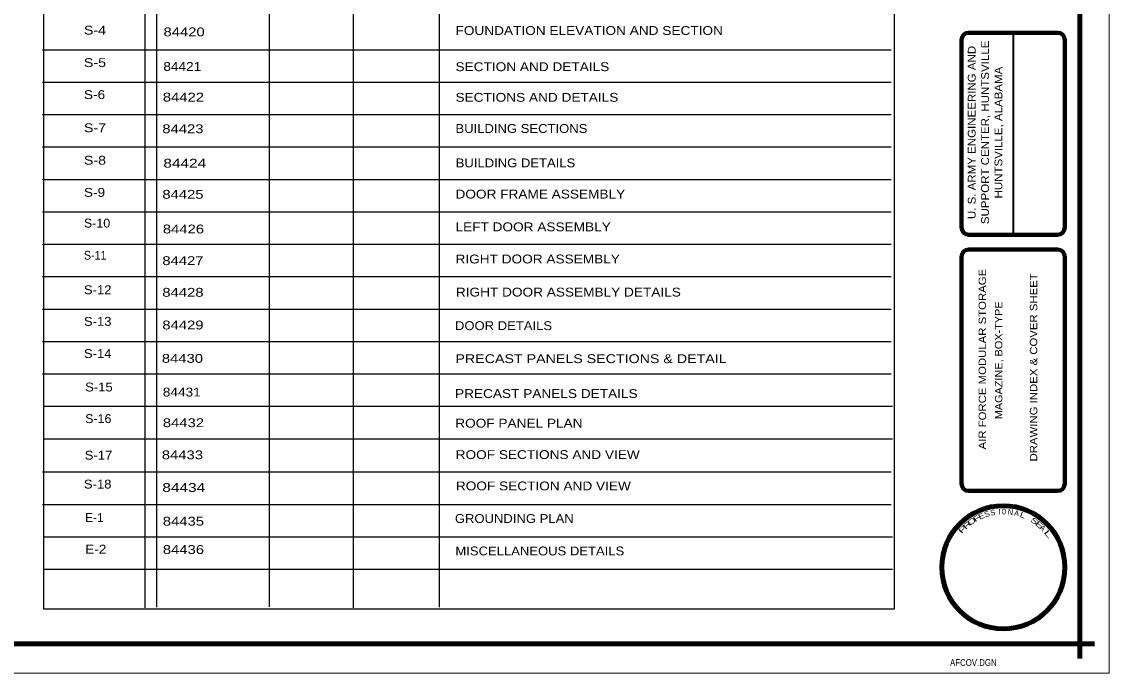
# Model space of a CAD drawing. Extents: x -153.1 to -120, y 360.9 to 384.2.
# Drawn here: x -137.36 to -119.98, y 360.85 to 371.27 of the extents above; entities that cross this region are included whole.
import ezdxf
from ezdxf.enums import TextEntityAlignment as Align

# ---------------------------------------------------------------- set-up
doc = ezdxf.new("R2010")
doc.units = 0
doc.header["$LTSCALE"] = 0.039
for name, color, linetype, lineweight in [('1', 7, 'Continuous', 80), ('3', 7, 'Continuous', 80), ('63', 7, 'Continuous', 25), ('8', 7, 'Continuous', 25)]:
    doc.layers.add(name, color=color, linetype=linetype, lineweight=lineweight)
doc.layers.add('7', color=7, linetype='Continuous')

msp = doc.modelspace()

# ---------------------------------------------------------------- linework, layer by layer
at = {"layer": '1'}
for p, q in [((-122.3375, 370.97314), (-122.3375, 367.98103)), ((-122.3375, 370.97314), (-122.3375, 367.98103)), ((-122.21937, 371.09124), (-120.80208, 371.09124)), ((-122.21937, 371.09124), (-120.80208, 371.09124)), ((-120.68396, 367.98103), (-120.68396, 370.97314)), ((-120.68396, 367.98103), (-120.68396, 370.97314)), ((-122.21937, 367.86293), (-120.80208, 367.86293)), ((-122.21937, 367.86293), (-120.80208, 367.86293)), ((-122.3375, 367.50859), (-122.3375, 363.8858)), ((-122.3375, 367.50859), (-122.3375, 363.8858)), ((-120.80208, 367.6267), (-122.21937, 367.6267)), ((-120.80208, 367.6267), (-122.21937, 367.6267)), ((-120.68396, 363.8858), (-120.68396, 367.50859)), ((-120.68396, 363.8858), (-120.68396, 367.50859)), ((-122.21937, 363.7677), (-120.80208, 363.7677)), ((-122.21937, 363.7677), (-120.80208, 363.7677))]:
    msp.add_line(p, q, dxfattribs=at)
at = {"layer": '1', "lineweight": 40}
msp.add_line((-121.51073, 371.09124), (-121.51073, 367.86293), dxfattribs=at)
msp.add_line((-121.51073, 371.09124), (-121.51073, 367.86293), dxfattribs=at)
at = {"layer": '1', "lineweight": 90}
msp.add_line((-120.44775, 361.32709), (-120.44775, 361.09086), dxfattribs=at)
msp.add_line((-120.44775, 361.32709), (-120.44775, 361.09086), dxfattribs=at)
msp.add_line((-120.44775, 361.32709), (-120.44775, 361.09086), dxfattribs=at)
at = {"layer": '1', "lineweight": 13}
msp.add_lwpolyline([(-153.08523, 360.85466), (-119.97531, 360.85466), (-119.97531, 384.24028), (-153.08523, 384.24028)], close=True, dxfattribs=at)
msp.add_lwpolyline([(-153.08523, 360.85466), (-119.97531, 360.85466), (-119.97531, 384.24028), (-153.08523, 384.24028)], close=True, dxfattribs=at)
msp.add_lwpolyline([(-153.08523, 360.85466), (-119.97531, 360.85466), (-119.97531, 384.24028), (-153.08523, 384.24028)], close=True, dxfattribs=at)
at = {"layer": '1', "lineweight": 90}
for points in [[(-152.02225, 383.76784), (-120.44775, 383.76784), (-120.44775, 361.32709)], [(-152.02225, 383.76784), (-120.44775, 383.76784), (-120.44775, 361.32709)], [(-152.02225, 383.76784), (-120.44775, 383.76784), (-120.44775, 361.32709)], [(-120.21152, 361.32709), (-120.44775, 361.32709), (-122.67215, 361.32709), (-152.02225, 361.32709)], [(-120.21152, 361.32709), (-120.44775, 361.32709), (-122.67215, 361.32709), (-152.02225, 361.32709)], [(-120.21152, 361.32709), (-120.44775, 361.32709), (-122.67215, 361.32709), (-152.02225, 361.32709)]]:
    msp.add_lwpolyline(points, dxfattribs=at)
msp.add_circle((-121.6682, 362.54754), 0.98424, dxfattribs=at)
msp.add_circle((-121.6682, 362.54754), 0.98424, dxfattribs=at)
at = {"layer": '1'}
for centre, start, end in [((-122.21937, 370.97314), 90, 180), ((-122.21937, 370.97314), 90, 180), ((-120.80206, 370.97314), 0, 90), ((-120.80206, 370.97314), 0, 90)]:
    msp.add_arc(centre, 0.11811, start, end, dxfattribs=at)
at = {"layer": '3'}
for centre, start, end in [((-122.21937, 367.98104), 180, 270), ((-122.21937, 367.98104), 180, 270), ((-120.80206, 367.98104), 270, 0), ((-120.80206, 367.98104), 270, 0), ((-122.21937, 367.5086), 90, 180), ((-122.21937, 367.5086), 90, 180), ((-120.80206, 367.5086), 0, 90), ((-120.80206, 367.5086), 0, 90), ((-122.21937, 363.8858), 180, 270), ((-122.21937, 363.8858), 180, 270), ((-120.80206, 363.8858), 270, 0), ((-120.80206, 363.8858), 270, 0)]:
    msp.add_arc(centre, 0.11811, start, end, dxfattribs=at)
at = {"layer": '63'}
msp.add_lwpolyline([(-137.00331, 374.8668), (-123.41131, 374.8668), (-123.41131, 361.87971), (-137.00331, 361.87971)], close=True, dxfattribs=at)
at = {"layer": '8'}
for p, q in [((-135.38806, 374.12059), (-135.38806, 361.89876)), ((-135.20612, 374.20461), (-135.20612, 361.90815)), ((-133.40354, 374.12059), (-133.40354, 361.91753)), ((-130.68806, 374.12059), (-130.68806, 361.90815)), ((-132.06006, 373.78197), (-132.06006, 361.89876)), ((-137.02615, 370.81895), (-123.46037, 370.81895)), ((-137.02615, 370.30093), (-123.46037, 370.30093)), ((-137.02615, 369.78291), (-123.46037, 369.78291)), ((-137.02615, 369.26491), (-123.46037, 369.26491)), ((-137.02615, 368.74689), (-123.46037, 368.74689)), ((-137.02615, 368.22886), (-123.46037, 368.22886)), ((-137.02615, 367.71084), (-123.46037, 367.71084)), ((-137.02615, 367.19284), (-123.46037, 367.19284)), ((-137.02615, 366.67482), (-123.46037, 366.67482)), ((-137.02615, 366.1568), (-123.46037, 366.1568)), ((-137.02615, 365.63878), (-123.46037, 365.63878)), ((-137.0066, 365.12076), (-123.44085, 365.12076)), ((-137.0066, 364.60276), (-123.44085, 364.60276)), ((-137.02615, 364.07118), (-123.46037, 364.07118)), ((-137.02615, 363.55316), (-123.46037, 363.55316)), ((-137.0066, 363.03516), (-123.44085, 363.03516)), ((-137.0066, 362.51714), (-123.44085, 362.51714))]:
    msp.add_line(p, q, dxfattribs=at)

# ---------------------------------------------------------------- texts
at = {"layer": '1', "width": 1.1}
for s, p in [('SUPPORT CENTER, HUNTSVILLE', (-121.8975, 369.49825)), ('SUPPORT CENTER, HUNTSVILLE', (-121.8975, 369.49825)), ('U. S. ARMY ENGINEERING AND', (-122.111, 369.49675)), ('U. S. ARMY ENGINEERING AND', (-122.111, 369.49675)), ('HUNTSVILLE, ALABAMA', (-121.68404, 369.49477)), ('HUNTSVILLE, ALABAMA', (-121.68404, 369.49477))]:
    msp.add_text(s, height=0.125, rotation=90, dxfattribs=at).set_placement(p, align=Align.CENTER)
at = {"layer": '3'}
for s, height, rotation, width, p in [('AIR FORCE MODULAR STORAGE', 0.1181, 90, 1.15, (-121.94504, 365.87451)), ('DRAWING INDEX & COVER SHEET', 0.1181, 90, 1.15, (-121.12606, 365.74304)), ('MAGAZINE, BOX-TYPE', 0.1181, 90, 1.1, (-121.68406, 365.85523)), ('I', 0.08771, 3.86, 1.05, (-121.72466, 363.39214)), ('I', 0.08771, 3.86, 1.05, (-121.72466, 363.39214)), ('O', 0.08771, 359.022, 0.65, (-121.65938, 363.39394)), ('O', 0.08771, 359.022, 0.65, (-121.65938, 363.39394)), ('N', 0.08772, 354.184, 0.8, (-121.55879, 363.3872)), ('N', 0.08772, 354.184, 0.8, (-121.55879, 363.3872)), ('A', 0.08771, 349.346, 0.95, (-121.4621, 363.37002)), ('A', 0.08771, 349.346, 0.95, (-121.4621, 363.37002)), ('R', 0.08771, 42.566, 1.65, (-122.21777, 363.19206)), ('R', 0.08771, 42.566, 1.65, (-122.21777, 363.19206)), ('O', 0.08771, 37.728, 1.4, (-122.14837, 363.24625)), ('O', 0.08771, 37.728, 1.4, (-122.14837, 363.24625)), ('F', 0.08771, 32.89, 1.65, (-122.06907, 363.2963)), ('F', 0.08771, 32.89, 1.65, (-122.06907, 363.2963)), ('E', 0.08772, 23.213, 1.25, (-122.00185, 363.32542)), ('E', 0.08772, 23.213, 1.25, (-122.00185, 363.32542)), ('S', 0.08771, 18.375, 1.1, (-121.91636, 363.35702)), ('S', 0.08771, 18.375, 1.1, (-121.91636, 363.35702)), ('L', 0.08771, 339.669, 1.4, (-121.3712, 363.34014)), ('L', 0.08771, 339.669, 1.4, (-121.3712, 363.34014)), ('S', 0.08771, 329.993, 1.4, (-121.194, 363.25111)), ('S', 0.08771, 329.993, 1.4, (-121.194, 363.25111)), ('E', 0.08771, 320.316, 1.7, (-121.11891, 363.1917)), ('E', 0.08771, 320.316, 1.7, (-121.11891, 363.1917)), ('P', 0.08771, 47.405, 1.8, (-122.2866, 363.12556)), ('P', 0.08771, 47.405, 1.8, (-122.2866, 363.12556)), ('L', 0.08771, 310.64, 2.05, (-120.98493, 363.05099)), ('L', 0.08771, 310.64, 2.05, (-120.98493, 363.05099))]:
    msp.add_text(s, height=height, rotation=rotation, dxfattribs=dict(at, width=width)).set_placement(p, align=Align.CENTER)
for s, rotation, p in [('S', 13.537, (-121.82746, 363.37977)), ('S', 13.537, (-121.82746, 363.37977)), ('A', 315.478, (-121.06938, 363.14579)), ('A', 315.478, (-121.06938, 363.14579))]:
    msp.add_text(s, height=0.08771, rotation=rotation, dxfattribs=at).set_placement(p, align=Align.CENTER)
at = {"layer": '3', "width": 0.85}
msp.add_text('AFCOV.DGN', height=0.1102, dxfattribs=at).set_placement((-122.14768, 360.97084), align=Align.CENTER)
at = {"layer": '63'}
for s, width, p in [('84421', 1.15, (-135.09437, 370.48064)), ('84422', 1.25, (-135.1024, 369.99082)), ('84423', 1.25, (-135.11042, 369.48495)), ('84424', 1.3, (-135.09437, 368.93494)), ('84425', 1.25, (-135.11042, 368.43709)), ('84426', 1.25, (-135.1024, 367.88305)), ('84427', 1.25, (-135.11042, 367.37718)), ('84428', 1.25, (-135.11042, 366.8713)), ('84429', 1.25, (-135.11042, 366.34938)), ('84430', 1.25, (-135.11845, 365.81543)), ('84431', 1.15, (-135.1024, 365.27744)), ('84432', 1.25, (-135.1024, 364.78762)), ('84433', 1.25, (-135.11845, 364.27372)), ('84434', 1.3, (-135.11042, 363.75179)), ('84435', 1.25, (-135.1024, 363.2138)), ('84436', 1.25, (-135.1024, 362.76094))]:
    msp.add_text(s, height=0.1417, dxfattribs=dict(at, width=width)).set_placement(p)
at = {"layer": '7'}
for s, width, p in [('S-4', 1.2, (-136.36356, 371.06099)), ('84420', 1.25, (-135.09154, 371.0332)), ('FOUNDATION ELEVATION AND SECTION', 1.15, (-130.42437, 371.05509)), ('S-5', 1.2, (-136.36356, 370.54232)), ('SECTION AND DETAILS', 1.15, (-130.42437, 370.47678)), ('S-6', 1.15, (-136.36356, 370.03057)), ('SECTIONS AND DETAILS', 1.15, (-130.42465, 369.98722)), ('S-7', 1.2, (-136.36356, 369.50078)), ('BUILDING SECTIONS', 1.1, (-130.42455, 369.48911)), ('S-8', 1.2, (-136.36356, 368.98222)), ('BUILDING DETAILS', 1.1, (-130.42095, 368.93944)), ('S-9', 1.15, (-136.36356, 368.46843)), ('DOOR FRAME ASSEMBLY', 1.15, (-130.42437, 368.44141)), ('S-10', 1.05, (-136.36356, 367.97753)), ('LEFT DOOR ASSEMBLY', 1.15, (-130.42437, 367.91768)), ('S-11', 0.9, (-136.36356, 367.46303)), ('RIGHT DOOR ASSEMBLY', 1.15, (-130.42437, 367.40389)), ('S-12', 1.1, (-136.36356, 366.91197)), ('RIGHT DOOR ASSEMBLY DETAILS', 1.15, (-130.41853, 366.875)), ('S-13', 1.1, (-136.36356, 366.40682)), ('DOOR DETAILS', 1.1, (-130.43282, 366.33873)), ('S-14', 1.1, (-136.36356, 365.89232)), ('PRECAST PANELS SECTIONS & DETAIL', 1.2, (-130.42491, 365.81098)), ('S-15', 1.1, (-136.34404, 365.35793)), ('PRECAST PANELS DETAILS', 1.15, (-130.4318, 365.25345)), ('S-16', 1.05, (-136.34404, 364.85276)), ('ROOF PANEL PLAN', 1.15, (-130.42836, 364.78028)), ('S-17', 1.1, (-136.34998, 364.26905)), ('ROOF SECTIONS AND VIEW', 1.15, (-130.42148, 364.27785)), ('S-18', 1.1, (-136.36356, 363.8067)), ('ROOF SECTION AND VIEW', 1.15, (-130.41804, 363.77718)), ('GROUNDING PLAN', 1.1, (-130.43473, 363.25597)), ('E-2', 1.15, (-136.34404, 362.76714)), ('MISCELLANEOUS DETAILS', 1.1, (-130.42611, 362.73805))]:
    msp.add_text(s, height=0.1417, dxfattribs=dict(at, width=width)).set_placement(p)
msp.add_text('E-1', height=0.1417, dxfattribs=at).set_placement((-136.34404, 363.2723))

doc.saveas('drawing.dxf')
